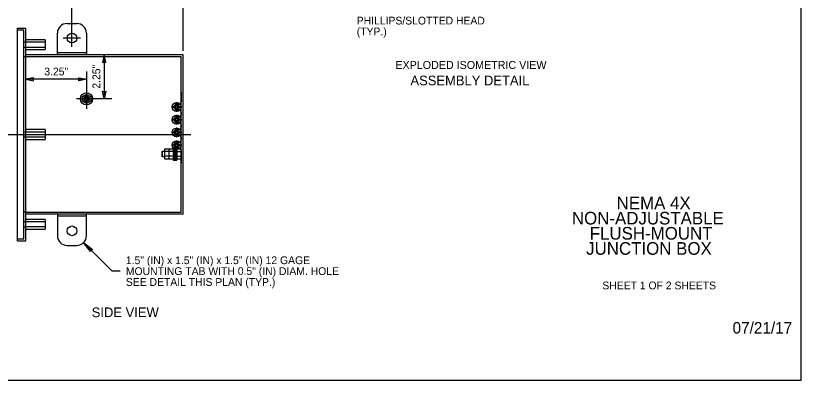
# Model space of a CAD drawing. Extents: x 99862 to 103151, y 100000 to 105076.
# Drawn here: x 101532 to 103151, y 100000 to 100750 of the extents above; entities that cross this region are included whole.
import ezdxf

# ---------------------------------------------------------------- set-up
doc = ezdxf.new("R2010")
doc.units = 0
for name, color, linetype in [('Level 1', 7, 'Continuous'), ('Level 15', 7, 'Continuous'), ('Level 2', 7, 'Continuous'), ('Level 20', 7, 'Continuous'), ('Level 3', 7, 'Continuous'), ('Level 62', 7, 'Continuous')]:
    doc.layers.add(name, color=color, linetype=linetype)

# ---------------------------------------------------------------- blocks, each defined once
blk = doc.blocks.new('T')
at = {"layer": 'Level 15'}
blk.add_lwpolyline([(0, 0), (-22.829, 2.985), (-21.773, 0), (-22.83, -2.985)], close=True, dxfattribs=at)

msp = doc.modelspace()

# ---------------------------------------------------------------- linework, layer by layer
at = {"layer": 'Level 1'}
msp.add_lwpolyline([(99862, 99999.5), (103151, 99999.5), (103151, 102075.5), (99862, 102075.5)], close=True, dxfattribs=at)
at = {"layer": 'Level 15'}
for p, q in [((101877.3, 100677.9), (101877.3, 100804.9)), ((101714.5, 100669.9), (101714.5, 100579.1)), ((101678.3, 100635.4), (101678.3, 100558.3)), ((101678.3, 100619.4), (101553.1, 100619.4)), ((101730.5, 100579.1), (101657.4, 100579.1)), ((101502.2, 100505.7), (101893.3, 100505.7)), ((101672.2, 100283.1), (101731.3, 100224.1)), ((101747.3, 100224.3), (101731.3, 100224.3))]:
    msp.add_line(p, q, dxfattribs=at)
msp.add_lwpolyline([(101672.2, 100283.1), (101690.5, 100269.1), (101687.6, 100267.8), (101686.3, 100264.9)], close=True, dxfattribs=at)
at = {"layer": 'Level 2'}
for p, q in [((101648.1, 100686.2), (101648.1, 100804.9)), ((101536.3, 100286.5), (101536.3, 100724.9)), ((101536.3, 100724.9), (101553.1, 100724.9)), ((101548.9, 100720.7), (101536.3, 100720.7)), ((101548.9, 100290.7), (101548.9, 100720.7)), ((101553.1, 100700.7), (101553.1, 100724.9)), ((101593.1, 100700.7), (101553.1, 100700.7)), ((101553.1, 100680.7), (101553.1, 100700.7)), ((101593.1, 100700.7), (101593.1, 100680.7)), ((101666.1, 100704.2), (101630.1, 100704.2)), ((101553.1, 100695.7), (101548.9, 100695.7)), ((101548.9, 100685.7), (101553.1, 100685.7)), ((101593.1, 100695.6), (101553.1, 100695.6)), ((101553.1, 100685.9), (101593.1, 100685.9)), ((101553.1, 100680.7), (101593.1, 100680.7)), ((101553.1, 100669.9), (101553.1, 100680.7)), ((101618.1, 100669.9), (101553.1, 100669.9)), ((101553.1, 100341.5), (101553.1, 100669.9)), ((101678.1, 100669.9), (101618.1, 100669.9)), ((101877.3, 100669.9), (101678.1, 100669.9)), ((101877.3, 100341.5), (101877.3, 100669.9)), ((101553.1, 100665.7), (101548.9, 100665.7)), ((101873.1, 100665.7), (101553.1, 100665.7)), ((101873.1, 100345.7), (101873.1, 100665.7)), ((101873.1, 100592.8), (101873.1, 100573)), ((101862.9, 100563.4), (101862.9, 100571)), ((101865, 100571), (101865, 100563.4)), ((101855.3, 100563.4), (101862.9, 100563.4)), ((101862.9, 100561.4), (101855.3, 100561.4)), ((101862.9, 100553.8), (101862.9, 100561.4)), ((101868.1, 100568), (101863.9, 100568)), ((101863.9, 100556.8), (101868.1, 100556.8)), ((101865, 100563.4), (101872.5, 100563.4)), ((101872.5, 100561.4), (101865, 100561.4)), ((101865, 100561.4), (101865, 100553.8)), ((101862.9, 100537.2), (101862.9, 100544.8)), ((101868.1, 100541.8), (101863.9, 100541.8)), ((101865, 100544.8), (101865, 100537.2)), ((101873.1, 100551.8), (101873.1, 100546.8)), ((101855.3, 100537.2), (101862.9, 100537.2)), ((101862.9, 100535.2), (101855.3, 100535.2)), ((101862.9, 100527.6), (101862.9, 100535.2)), ((101863.9, 100530.6), (101868.1, 100530.6)), ((101865, 100537.2), (101872.5, 100537.2)), ((101872.5, 100535.2), (101865, 100535.2)), ((101865, 100535.2), (101865, 100527.6)), ((101873.1, 100525.6), (101873.1, 100520.5)), ((101553.1, 100510.7), (101548.9, 100510.7)), ((101593.1, 100515.7), (101553.1, 100515.7)), ((101593.1, 100510.6), (101553.1, 100510.6)), ((101593.1, 100515.7), (101593.1, 100495.7)), ((101855.3, 100511), (101862.9, 100511)), ((101862.9, 100508.9), (101855.3, 100508.9)), ((101862.9, 100511), (101862.9, 100518.5)), ((101862.9, 100501.4), (101862.9, 100508.9)), ((101868.1, 100515.5), (101863.9, 100515.5)), ((101865, 100518.5), (101865, 100511)), ((101865, 100511), (101872.5, 100511)), ((101872.5, 100508.9), (101865, 100508.9)), ((101865, 100508.9), (101865, 100501.4)), ((101548.9, 100500.7), (101553.1, 100500.7)), ((101553.1, 100500.9), (101593.1, 100500.9)), ((101553.1, 100495.7), (101593.1, 100495.7)), ((101862.9, 100484.7), (101862.9, 100492.3)), ((101863.9, 100504.3), (101868.1, 100504.3)), ((101868.1, 100489.3), (101863.9, 100489.3)), ((101865, 100492.3), (101865, 100484.7)), ((101873.1, 100499.3), (101873.1, 100494.3)), ((101855.3, 100484.7), (101862.9, 100484.7)), ((101862.9, 100482.7), (101855.3, 100482.7)), ((101862.9, 100475.1), (101862.9, 100482.7)), ((101863.9, 100478.1), (101868.1, 100478.1)), ((101865, 100484.7), (101872.5, 100484.7)), ((101872.5, 100482.7), (101865, 100482.7)), ((101865, 100482.7), (101865, 100475.1)), ((101873.1, 100473.1), (101873.1, 100446.8)), ((101553.1, 100345.7), (101548.9, 100345.7)), ((101553.1, 100345.7), (101873.1, 100345.7)), ((101618.1, 100341.5), (101553.1, 100341.5)), ((101553.1, 100330.7), (101553.1, 100341.5)), ((101593.1, 100330.7), (101553.1, 100330.7)), ((101553.1, 100310.7), (101553.1, 100330.7)), ((101593.1, 100330.7), (101593.1, 100310.7)), ((101678.1, 100341.5), (101618.1, 100341.5)), ((101877.3, 100341.5), (101678.1, 100341.5)), ((101553.1, 100325.7), (101548.9, 100325.7)), ((101548.9, 100315.7), (101553.1, 100315.7)), ((101593.1, 100325.6), (101553.1, 100325.6)), ((101553.1, 100315.9), (101593.1, 100315.9)), ((101553.1, 100286.5), (101553.1, 100310.7)), ((101553.1, 100310.7), (101593.1, 100310.7)), ((101536.3, 100290.7), (101548.9, 100290.7)), ((101536.3, 100286.5), (101553.1, 100286.5))]:
    msp.add_line(p, q, dxfattribs=at)
for centre, radius in [((101678.3, 100579.2), 4.86), ((101863.9, 100562.4), 9.15), ((101863.9, 100562.4), 5), ((101863.9, 100536.2), 9.15), ((101863.9, 100536.2), 5), ((101863.9, 100509.9), 9.15), ((101863.9, 100509.9), 5), ((101863.9, 100483.7), 9.15), ((101863.9, 100483.7), 5)]:
    msp.add_circle(centre, radius, dxfattribs=at)
for centre, radius, start, end in [((101863.9, 100562.4), 8.66, 83.1584, 96.8416), ((101868.1, 100573), 5, 270, 0), ((101863.9, 100562.4), 8.66, 173.1584, 186.8416), ((101863.9, 100562.4), 5.6, 90, 270), ((101868.1, 100551.8), 5, 0, 90), ((101863.9, 100562.4), 8.66, 353.1584, 6.8416), ((101863.9, 100536.2), 5.6, 90, 270), ((101863.9, 100562.4), 8.66, 263.1584, 276.8416), ((101863.9, 100536.2), 8.66, 83.1584, 96.8416), ((101868.1, 100546.8), 5, 270, 360), ((101863.9, 100536.2), 8.66, 173.1584, 186.8416), ((101863.9, 100536.2), 8.66, 263.1584, 276.8416), ((101868.1, 100525.6), 5, 0, 90), ((101863.9, 100536.2), 8.66, 353.1584, 6.8416), ((101863.9, 100509.9), 8.66, 173.1584, 186.8416), ((101863.9, 100509.9), 5.6, 90, 270), ((101863.9, 100509.9), 8.66, 83.1584, 96.8416), ((101868.1, 100520.5), 5, 270, 360), ((101863.9, 100509.9), 8.66, 353.1584, 6.8416), ((101863.9, 100483.7), 5.6, 90, 270), ((101863.9, 100509.9), 8.66, 263.1584, 276.8416), ((101863.9, 100483.7), 8.66, 83.1584, 96.8416), ((101868.1, 100499.3), 5, 360, 90), ((101868.1, 100494.3), 5, 270, 360), ((101863.9, 100483.7), 8.66, 173.1584, 186.8416), ((101863.9, 100483.7), 8.66, 263.1584, 276.8416), ((101868.1, 100473.1), 5, 0, 90), ((101863.9, 100483.7), 8.66, 353.1584, 6.8416)]:
    msp.add_arc(centre, radius, start, end, dxfattribs=at)
at = {"layer": 'Level 3'}
for p, q in [((101638.1, 100734.2), (101658.1, 100734.2)), ((101618.1, 100669.9), (101618.1, 100714.2)), ((101678.1, 100714.2), (101678.1, 100669.9)), ((101678.1, 100674.2), (101618.1, 100674.2)), ((101669.6, 100584.1), (101678.3, 100589.1)), ((101678.3, 100589.1), (101687, 100584.1)), ((101669.6, 100574.3), (101669.6, 100584.1)), ((101678.3, 100569.3), (101669.6, 100574.3)), ((101687, 100574.3), (101678.3, 100569.3)), ((101687, 100584.1), (101687, 100574.3)), ((101847.7, 100475.7), (101839, 100475.7)), ((101839, 100475.7), (101839, 100470.9)), ((101847.7, 100475.7), (101847.7, 100470.7)), ((101856.5, 100475.7), (101847.7, 100475.7)), ((101859.1, 100478.3), (101856.5, 100478.3)), ((101856.5, 100478.3), (101856.5, 100475.7)), ((101856.5, 100475.7), (101856.5, 100455.8)), ((101859.1, 100478.3), (101859.1, 100453.1)), ((101861.7, 100478.3), (101859.1, 100478.3)), ((101861.7, 100478.3), (101861.7, 100453.1)), ((101864.3, 100478.3), (101861.7, 100478.3)), ((101864.3, 100475.7), (101864.3, 100478.3)), ((101864.3, 100475.7), (101864.3, 100455.8)), ((101873.1, 100475.7), (101864.3, 100475.7)), ((101873.1, 100470.7), (101873.1, 100475.7)), ((101834, 100470.9), (101833.1, 100470)), ((101833.1, 100470), (101833.1, 100461.4)), ((101833.1, 100461.4), (101834, 100460.5)), ((101834, 100470.9), (101834, 100460.5)), ((101839, 100470.9), (101834, 100470.9)), ((101834, 100460.5), (101839, 100460.5)), ((101839, 100470.9), (101839, 100470.7)), ((101847.7, 100470.7), (101839, 100470.7)), ((101839, 100470.7), (101839, 100460.8)), ((101847.7, 100460.8), (101839, 100460.8)), ((101839, 100460.8), (101839, 100460.5)), ((101839, 100460.5), (101839, 100455.8)), ((101856.5, 100470.7), (101847.7, 100470.7)), ((101847.7, 100470.7), (101847.7, 100460.8)), ((101856.5, 100460.8), (101847.7, 100460.8)), ((101847.7, 100460.8), (101847.7, 100455.8)), ((101864.3, 100470.7), (101873.1, 100470.7)), ((101873.1, 100460.7), (101864.3, 100460.7)), ((101873.1, 100460.8), (101873.1, 100470.7)), ((101873.1, 100455.8), (101873.1, 100460.8)), ((101839, 100455.8), (101847.7, 100455.8)), ((101847.7, 100455.8), (101856.5, 100455.8)), ((101856.5, 100455.8), (101856.5, 100453.1)), ((101856.5, 100453.1), (101859.1, 100453.1)), ((101859.1, 100453.1), (101861.7, 100453.1)), ((101861.7, 100453.1), (101864.3, 100453.1)), ((101864.3, 100453.1), (101864.3, 100455.8)), ((101864.3, 100455.8), (101873.1, 100455.8)), ((101618.1, 100341.5), (101618.1, 100297.3)), ((101678.1, 100337.3), (101618.1, 100337.3)), ((101678.1, 100297.3), (101678.1, 100341.5)), ((101638.1, 100277.3), (101658.1, 100277.3))]:
    msp.add_line(p, q, dxfattribs=at)
for centre, radius in [((101648.1, 100704.2), 10), ((101678.3, 100579.2), 12.5), ((101678.3, 100579.2), 5.62), ((101678.3, 100579.2), 5), ((101678.3, 100579.1), 3.09), ((101648.1, 100307.3), 10)]:
    msp.add_circle(centre, radius, dxfattribs=at)
for centre, start, end in [((101638.1, 100714.2), 90, 180), ((101658.1, 100714.2), 360, 90), ((101638.1, 100297.3), 180, 270), ((101658.1, 100297.3), 270, 360)]:
    msp.add_arc(centre, 20, start, end, dxfattribs=at)

# ---------------------------------------------------------------- block references
at = {"layer": 'Level 15', "xscale": 0.700832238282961}
for p, yscale, rotation in [((101714.5, 100669.9), 1.0720268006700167, 90), ((101553.1, 100619.4), 1.0720268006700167, 180), ((101714.5, 100579.1), -1.0720268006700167, -90)]:
    msp.add_blockref('T', p, dxfattribs=dict(at, yscale=yscale, rotation=rotation))
at = {"layer": 'Level 15', "xscale": 0.700832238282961, "yscale": -1.0720268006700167}
msp.add_blockref('T', (101678.3, 100619.4), dxfattribs=at)

# ---------------------------------------------------------------- texts
at = {"layer": 'Level 15'}
for s, height, p in [('PHILLIPS/SLOTTED HEAD', 16, (102235, 100732.3)), ('(TYP.)', 16, (102235, 100709.9)), ('07/21/17', 23.62, (103009.4, 100095.8))]:
    msp.add_text(s, height=height, dxfattribs=at).set_placement(p)
at = {"layer": 'Level 20'}
for s, height, p in [('EXPLODED ISOMETRIC VIEW', 16.5, (102314.6, 100640.7)), ('3.25"', 16, (101591.2, 100627.4)), ('ASSEMBLY DETAIL', 20, (102345.6, 100607)), ('SIDE VIEW', 20, (101688.9, 100129.5))]:
    msp.add_text(s, height=height, dxfattribs=at).set_placement(p)
for s, rotation, p in [('2.25"', 90, (101706.5, 100600.1)), ('1.5" (IN) x 1.5" (IN) x 1.5" (IN) 12 GAGE', 360, (101759.3, 100238.7)), ('MOUNTING TAB WITH 0.5" (IN) DIAM. HOLE', 360, (101759.3, 100216.3)), ('SEE DETAIL THIS PLAN (TYP.)', 360, (101759.3, 100193.9))]:
    msp.add_text(s, height=16, rotation=rotation, dxfattribs=at).set_placement(p)
at = {"layer": 'Level 62'}
for s, height, p in [('NEMA 4X', 26, (102770.5, 100351.6)), ('NON-ADJUSTABLE', 26, (102678.3, 100320.4)), ('FLUSH-MOUNT', 26, (102715.1, 100289.2)), ('JUNCTION BOX', 26, (102707.7, 100258)), ('SHEET 1 OF 2 SHEETS', 16, (102741.1, 100186.8))]:
    msp.add_text(s, height=height, dxfattribs=at).set_placement(p)

doc.saveas('drawing.dxf')
